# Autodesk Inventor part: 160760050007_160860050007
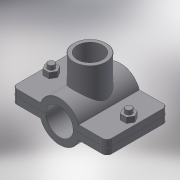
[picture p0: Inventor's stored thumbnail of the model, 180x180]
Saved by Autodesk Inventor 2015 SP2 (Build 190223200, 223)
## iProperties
Created: 2017-05
Part Number: 160760050007_160860050007
Material: Generic
Description: PLASSON SADDLE 50-3/4"
Document SubType Name: Modeling
Designer: KIM
Density: 1 g/cm^3
Appearance: Default
Author: KIM
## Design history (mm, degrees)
derived "16076.ipt"
feature "Solid1::16076.ipt"
feature "Solid2::16076.ipt"
tag "TaggingFeature1"
body "Solid1"
other parameters: "d1" = 106, "d2" = 25, "d4" = 73, "d5" = 0, "d6" = 5.3, "d7" = 106, "d8" = 0.1, "d10" = 0, "d11" = 0.5, "d14" = 31.3521, "d20" = 0.5, "d23" = 0.5, "d37" = 8, "d38" = 33, "d39" = 0, "d40" = 3, "d41" = 5, "d42" = 0, "d43" = 6, "d44" = 3, "d45" = 0, "d46" = 0.5, "d51" = 52, "d52" = 24.117, "d53" = 19, "d54" = 0, "d55" = 21, "d57" = 0, "d58" = 54, "d60" = 0, "d63" = 36.5, "d66" = 0, "B_" = 21, "G_" = 24.117, "A_" = 52, "L_" = 106, "L_1" = 73, "l_2" = 19
